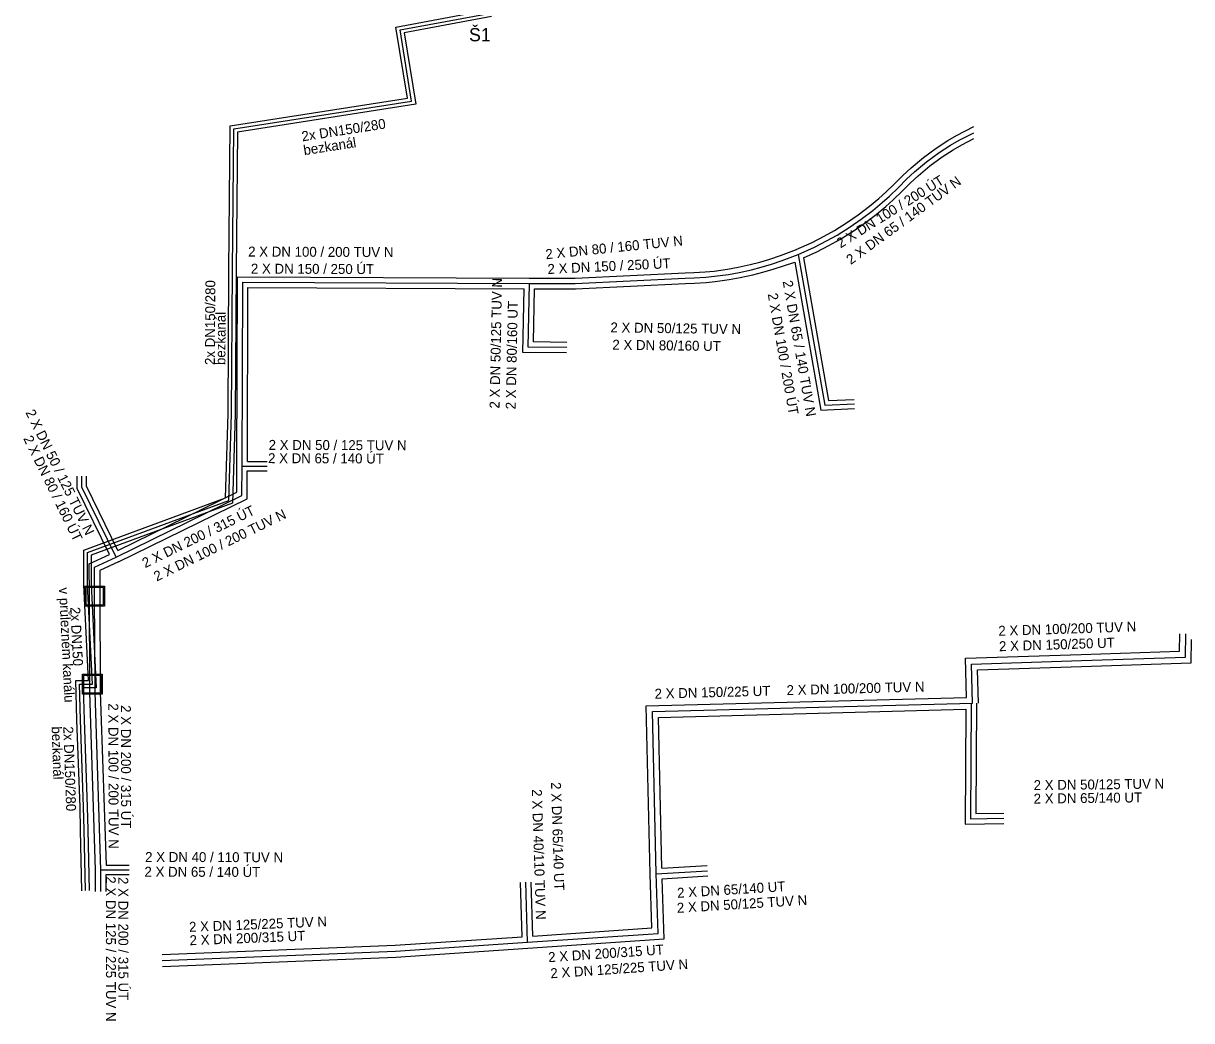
# Model space of a CAD drawing. Extents: x -606118 to -604472, y -1157869 to -1156854.
# Drawn here: x -604682.2 to -604505.6, y -1157189.1 to -1157038.5 of the extents above; entities that cross this region are included whole.
import ezdxf

# ---------------------------------------------------------------- set-up
doc = ezdxf.new("R2010")
doc.units = 0
for name, color, linetype in [('Osa trasy teplovodu', 7, 'Continuous'), ('označení šachty', 7, 'Continuous'), ('Teplovod - trasa - okraj', 7, 'Continuous'), ('Teplovod - trasa popis', 7, 'Continuous'), ('Teplovod - trasa popis 2', 7, 'Continuous'), ('Šachta trasy teplovodu', 7, 'Continuous')]:
    doc.layers.add(name, color=color, linetype=linetype)

msp = doc.modelspace()

# ---------------------------------------------------------------- linework, layer by layer
at = {"layer": 'Osa trasy teplovodu'}
for p, q in [((-604649.15, -1157105.36), (-604645.35, -1157105.37)), ((-604671.38, -1157138.68), (-604671.44, -1157125.03)), ((-604670.5, -1157166.35), (-604666.2, -1157166.36)), ((-604670.5, -1157169.65), (-604670.5, -1157166.35)), ((-604586.57, -1157166.97), (-604578.82, -1157166.49)), ((-604606, -1157177.31), (-604606.28, -1157168.25))]:
    msp.add_line(p, q, dxfattribs=at)
for points in [[(-604672.51, -1157123.29), (-604672.53, -1157122.83), (-604672.53, -1157118.43), (-604651.14, -1157110.56), (-604650.73, -1157097.49), (-604650.61, -1157075.79), (-604650.42, -1157054.42), (-604623.53, -1157050.24), (-604625.27, -1157039.47), (-604611.57, -1157036.91)], [(-604565.09, -1157073.39), (-604562.64, -1157072.29), (-604560.81, -1157071.35), (-604559.22, -1157070.46), (-604557.22, -1157069.2), (-604555.58, -1157068.07), (-604553.82, -1157066.73), (-604552.4, -1157065.55), (-604551.29, -1157064.56), (-604549.96, -1157063.28), (-604548.73, -1157062.03), (-604547.5, -1157060.89), (-604545.69, -1157059.38), (-604543.81, -1157058), (-604542.07, -1157056.88), (-604540.76, -1157056.12), (-604539.48, -1157055.45), (-604538.56, -1157055)], [(-604605.72, -1157077.76), (-604598.79, -1157077.78), (-604582.16, -1157076.99), (-604580.82, -1157076.94), (-604579.07, -1157076.82), (-604577.73, -1157076.68), (-604575.65, -1157076.4), (-604574.03, -1157076.1), (-604572.15, -1157075.69), (-604570.67, -1157075.31), (-604569.13, -1157074.86), (-604567.52, -1157074.32), (-604565.09, -1157073.39)], [(-604565.09, -1157073.39), (-604561.09, -1157096.17), (-604556.6, -1157095.98)], [(-604649.15, -1157105.36), (-604649.06, -1157077.59), (-604605.78, -1157077.76)], [(-604600.09, -1157087.47), (-604605.93, -1157087.4), (-604605.72, -1157077.76)], [(-604668.18, -1157119.13), (-604649.17, -1157109.8), (-604649.15, -1157105.36)], [(-604668.18, -1157119.13), (-604673.36, -1157108.57), (-604673.36, -1157106.88)], [(-604671.44, -1157125.03), (-604671.45, -1157120.62), (-604668.18, -1157119.13)], [(-604672.71, -1157138.31), (-604671.78, -1157138.31), (-604672.51, -1157123.29)], [(-604538.74, -1157141.19), (-604538.91, -1157135.27), (-604522.28, -1157134.73), (-604506.56, -1157134.22), (-604506.52, -1157130.73)], [(-604672.83, -1157169.49), (-604673.03, -1157160.33), (-604673.1, -1157156.85), (-604673.56, -1157143.71), (-604673.73, -1157138.31), (-604672.71, -1157138.31)], [(-604670.5, -1157166.35), (-604671.38, -1157139.5), (-604671.38, -1157138.68)], [(-604586.57, -1157166.94), (-604587.14, -1157142.45), (-604538.74, -1157141.19)], [(-604538.95, -1157141.19), (-604539.06, -1157158.64), (-604534, -1157158.58)], [(-604606, -1157177.31), (-604586.28, -1157175.97), (-604586.57, -1157166.94)], [(-604661.21, -1157180.07), (-604625.97, -1157178.66), (-604606, -1157177.31)]]:
    msp.add_lwpolyline(points, dxfattribs=at)
at = {"layer": 'Teplovod - trasa - okraj'}
for p, q in [((-604648.35, -1157104.66), (-604645.35, -1157104.67)), ((-604648.36, -1157106.06), (-604645.36, -1157106.07)), ((-604672.18, -1157138.69), (-604672.24, -1157125.03)), ((-604670.64, -1157125.03), (-604670.58, -1157138.68)), ((-604671.3, -1157169.65), (-604671.3, -1157166.35)), ((-604669.72, -1157165.65), (-604666.2, -1157165.66)), ((-604585.69, -1157166.11), (-604578.87, -1157165.69)), ((-604669.7, -1157167.05), (-604666.2, -1157167.06)), ((-604669.7, -1157169.65), (-604669.7, -1157167.05)), ((-604606.82, -1157176.47), (-604607.08, -1157168.28)), ((-604605.22, -1157176.36), (-604605.48, -1157168.23)), ((-604585.65, -1157167.71), (-604578.77, -1157167.29))]:
    msp.add_line(p, q, dxfattribs=at)
for points in [[(-604673.06, -1157123.32), (-604673.08, -1157122.85), (-604673.08, -1157118.05), (-604651.68, -1157110.17), (-604651.28, -1157097.48), (-604651.16, -1157075.79), (-604650.97, -1157053.95), (-604624.16, -1157049.78), (-604625.9, -1157039.03), (-604612.22, -1157036.47)], [(-604611.47, -1157037.45), (-604624.64, -1157039.91), (-604622.9, -1157050.69), (-604649.87, -1157054.89), (-604650.06, -1157075.8), (-604650.18, -1157097.5), (-604650.6, -1157110.95), (-604671.98, -1157118.82), (-604671.98, -1157122.82), (-604671.96, -1157123.27)], [(-604565.41, -1157072.66), (-604562.98, -1157071.57), (-604561.19, -1157070.65), (-604559.63, -1157069.77), (-604557.66, -1157068.53), (-604556.05, -1157067.42), (-604554.32, -1157066.11), (-604552.92, -1157064.94), (-604551.83, -1157063.97), (-604550.52, -1157062.71), (-604549.28, -1157061.46), (-604548.03, -1157060.29), (-604546.18, -1157058.75), (-604544.26, -1157057.34), (-604542.48, -1157056.19), (-604541.15, -1157055.42), (-604538.56, -1157054.06)], [(-604564.29, -1157073.91), (-604562.29, -1157073.01), (-604560.44, -1157072.06), (-604558.82, -1157071.14), (-604556.78, -1157069.87), (-604555.11, -1157068.72), (-604553.33, -1157067.36), (-604551.87, -1157066.15), (-604550.75, -1157065.15), (-604549.4, -1157063.85), (-604548.17, -1157062.61), (-604546.97, -1157061.49), (-604545.2, -1157060.01), (-604543.35, -1157058.66), (-604541.65, -1157057.56), (-604540.37, -1157056.82), (-604538.55, -1157055.86)], [(-604605.72, -1157076.96), (-604598.81, -1157076.98), (-604582.19, -1157076.19), (-604580.86, -1157076.14), (-604579.14, -1157076.02), (-604577.82, -1157075.89), (-604575.77, -1157075.6), (-604574.18, -1157075.32), (-604572.34, -1157074.92), (-604570.88, -1157074.54), (-604569.37, -1157074.09), (-604567.79, -1157073.57), (-604565.37, -1157072.64)], [(-604604.94, -1157078.56), (-604598.77, -1157078.58), (-604582.13, -1157077.79), (-604580.78, -1157077.74), (-604579, -1157077.62), (-604577.63, -1157077.48), (-604575.52, -1157077.19), (-604573.87, -1157076.89), (-604571.96, -1157076.47), (-604570.45, -1157076.08), (-604568.89, -1157075.62), (-604565.6, -1157074.53)], [(-604565.6, -1157074.53), (-604561.68, -1157096.9), (-604556.57, -1157096.68)], [(-604564.29, -1157073.91), (-604560.51, -1157095.45), (-604556.63, -1157095.28)], [(-604649.95, -1157105.35), (-604649.86, -1157076.79), (-604605.78, -1157076.96)], [(-604648.35, -1157104.66), (-604648.26, -1157078.39), (-604606.54, -1157078.56)], [(-604600.1, -1157088.27), (-604606.74, -1157088.19), (-604606.54, -1157078.56)], [(-604600.08, -1157086.67), (-604605.11, -1157086.61), (-604604.94, -1157078.56)], [(-604667.91, -1157118.1), (-604649.97, -1157109.3), (-604649.95, -1157105.35)], [(-604667.83, -1157119.84), (-604648.37, -1157110.3), (-604648.36, -1157106.06)], [(-604669.17, -1157118.7), (-604674.06, -1157108.73), (-604674.06, -1157106.88)], [(-604667.91, -1157118.1), (-604672.66, -1157108.41), (-604672.66, -1157106.88)], [(-604672.24, -1157125.03), (-604672.26, -1157120.11), (-604669.17, -1157118.7)], [(-604667.85, -1157119.85), (-604670.65, -1157121.13), (-604670.64, -1157125.03)], [(-604672.71, -1157137.76), (-604672.36, -1157137.76), (-604673.06, -1157123.32)], [(-604671.96, -1157123.27), (-604671.21, -1157138.86), (-604672.71, -1157138.86)], [(-604539.67, -1157140.31), (-604539.83, -1157134.4), (-604522.31, -1157133.83), (-604507.45, -1157133.35), (-604507.42, -1157130.72)], [(-604537.84, -1157141.16), (-604537.98, -1157136.14), (-604522.25, -1157135.63), (-604505.68, -1157135.09), (-604505.63, -1157131.55)], [(-604673.38, -1157169.51), (-604673.58, -1157160.35), (-604673.65, -1157156.87), (-604674.11, -1157143.72), (-604674.3, -1157137.76), (-604672.71, -1157137.76)], [(-604672.71, -1157138.86), (-604673.16, -1157138.86), (-604673.01, -1157143.69), (-604672.55, -1157156.84), (-604672.48, -1157160.32), (-604672.28, -1157169.48)], [(-604671.3, -1157166.37), (-604672.18, -1157139.52), (-604672.18, -1157138.69)], [(-604670.58, -1157138.68), (-604670.58, -1157139.49), (-604669.72, -1157165.65)], [(-604587.47, -1157166.96), (-604588.07, -1157141.57), (-604539.67, -1157140.31)], [(-604538.15, -1157141.2), (-604538.25, -1157157.83), (-604534.01, -1157157.78)], [(-604585.69, -1157166.11), (-604586.22, -1157143.33), (-604539.76, -1157142.11)], [(-604539.76, -1157142.11), (-604539.86, -1157159.45), (-604533.99, -1157159.38)], [(-604605.94, -1157178.21), (-604585.35, -1157176.8), (-604585.65, -1157167.71)], [(-604605.22, -1157176.36), (-604587.21, -1157175.13), (-604587.47, -1157166.97)], [(-604661.25, -1157179.17), (-604626.02, -1157177.76), (-604606.82, -1157176.47)], [(-604661.17, -1157180.97), (-604625.93, -1157179.55), (-604605.94, -1157178.21)]]:
    msp.add_lwpolyline(points, dxfattribs=at)
at = {"layer": 'Šachta trasy teplovodu'}
for points in [[(-604672.94, -1157126.53), (-604672.94, -1157123.52), (-604669.93, -1157123.52), (-604669.93, -1157126.53), (-604672.94, -1157126.53)], [(-604670.12, -1157126.34), (-604670.12, -1157123.71), (-604672.75, -1157123.71), (-604672.75, -1157126.34), (-604670.12, -1157126.34)], [(-604673.29, -1157139.81), (-604673.29, -1157136.81), (-604670.28, -1157136.81), (-604670.28, -1157139.81), (-604673.29, -1157139.81)], [(-604670.47, -1157139.62), (-604670.47, -1157136.99), (-604673.1, -1157136.99), (-604673.1, -1157139.62), (-604670.47, -1157139.62)]]:
    msp.add_lwpolyline(points, dxfattribs=at)

# ---------------------------------------------------------------- texts
at = {"layer": 'označení šachty'}
msp.add_text('Š1', height=2, dxfattribs=at).set_placement((-604614.85, -1157041.19))
at = {"layer": 'Teplovod - trasa popis'}
for s, rotation, p in [('2x DN150/280', 8.8473, (-604640.03, -1157056.31)), ('2 X DN 100 / 200 ÚT', 32.0283, (-604558.7, -1157072.49)), ('2 X DN 150 / 250 ÚT ', 359.7602, (-604647.82, -1157076.28)), ('2 X DN 150 / 250 ÚT ', 2.7502, (-604602.95, -1157076.35)), ('2x DN150/280', 89.6733, (-604653.27, -1157090.1)), ('2 X DN 100 / 200 ÚT', 279.9472, (-604569.71, -1157079.36)), ('2 X DN 80/160 UT', 88.8085, (-604607.81, -1157096.81)), ('2 X DN 80/160 UT', 359.2445, (-604593.19, -1157087.77)), ('2 X DN 80 / 160 ÚT ', 296.1046, (-604682.26, -1157101.2)), ('2 X DN 65 / 140 ÚT', 359.8175, (-604645.23, -1157104.92)), ('2 X DN 200 / 315 ÚT ', 26.1269, (-604663.8, -1157120.79)), ('2x DN150', 272.7698, (-604675.12, -1157126.69)), ('2 X DN 150/250 UT ', 1.8335, (-604534.72, -1157133.34)), ('2 X DN 150/225 UT ', 1.4897, (-604586.78, -1157140.51)), ('2 X DN 200 / 315 ÚT ', 270.0923, (-604667.47, -1157141.48)), ('2x DN150/280', 272.0021, (-604676.18, -1157144.72)), ('2 X DN 65/140 UT', 271.8112, (-604602.46, -1157153.14)), ('2 X DN 65/140 UT', 0.6875, (-604529.5, -1157156.36)), ('2 X DN 65 / 140 ÚT', 359.8748, (-604663.91, -1157167.4)), ('2 X DN 200 / 315 ÚT ', 270.0923, (-604667.87, -1157167.45)), ('2 X DN 65/140 UT', 3.5523, (-604583.35, -1157170.6)), ('2 X DN 200/315 UT ', 2.2918, (-604657.06, -1157177.76)), ('2 X DN 200/315 UT ', 3.8961, (-604602.83, -1157180.32))]:
    msp.add_text(s, height=1.5, rotation=rotation, dxfattribs=at).set_placement(p)
at = {"layer": 'Teplovod - trasa popis 2'}
for s, rotation, p in [('bezkanál', 8.8473, (-604639.76, -1157058.4)), ('2 X DN 65 / 140 TUV N', 36.2109, (-604557.14, -1157074.99)), ('2 X DN 80 / 160 TUV N', 5.7869, (-604603.22, -1157074.12)), ('2 X DN 100 / 200 TUV N', 359.7602, (-604648.24, -1157073.7)), ('2 X DN 50/125 TUV N', 88.8085, (-604610.25, -1157096.69)), ('2 X DN 65 / 140 TUV N', 279.9472, (-604567.45, -1157077.45)), ('bezkanál', 89.6733, (-604651.68, -1157090.1)), ('2 X DN 50/125 TUV N', 359.2445, (-604593.48, -1157085.16)), ('2 X DN 50 / 125 TUV N', 296.1046, (-604681.93, -1157097.25)), ('2 X DN 50 / 125 TUV N', 359.8175, (-604645.14, -1157102.91)), ('2 X DN 100 / 200 TUV N', 26.1269, (-604662.05, -1157122.82)), ('v průlezném kanálu', 272.7698, (-604676.83, -1157123.74)), ('2 X DN 100/200 TUV N', 1.8335, (-604534.82, -1157131.01)), ('2 X DN 100/200 TUV N', 1.4897, (-604566.83, -1157139.97)), ('2 X DN 100 / 200 TUV N', 270.0923, (-604669.36, -1157141.21)), ('bezkanál', 272.0021, (-604677.95, -1157144.72)), ('2 X DN 40/110 TUV N', 271.8112, (-604605.35, -1157154.2)), ('2 X DN 50/125 TUV N', 0.6875, (-604529.5, -1157154.32)), ('2 X DN 40 / 110 TUV N', 359.8748, (-604663.81, -1157165.17)), ('2 X DN 125 / 225 TUV N', 270.0923, (-604669.75, -1157167.34)), ('2 X DN 50/125 TUV N', 3.5523, (-604583.39, -1157172.87)), ('2 X DN 125/225 TUV N', 2.2918, (-604657.14, -1157175.74)), ('2 X DN 125/225 TUV N', 3.8961, (-604602.5, -1157182.75))]:
    msp.add_text(s, height=1.5, rotation=rotation, dxfattribs=at).set_placement(p)

doc.saveas('drawing.dxf')
